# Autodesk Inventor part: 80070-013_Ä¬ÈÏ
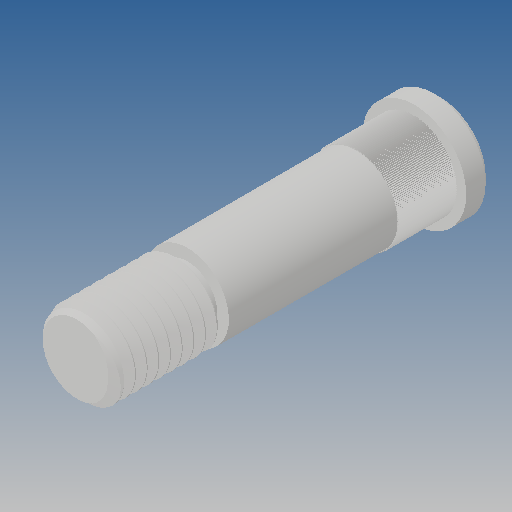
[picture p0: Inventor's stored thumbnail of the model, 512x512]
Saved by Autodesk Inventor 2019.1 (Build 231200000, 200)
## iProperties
Created: 2010-06
Part Number: 80070-013_Ä¬ÈÏ
Material: Ogólny
Document SubType Name: Modeling
Designer: CADENGINEERING4
Density: 1 g/cm^3
Appearance: Domyślna
Author: CADENGINEERING4
Revision Number: ÈÎºÎ
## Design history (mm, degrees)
feature "NONE"
node "Bryła1"
